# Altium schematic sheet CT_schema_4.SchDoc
size 573 x 376 mm
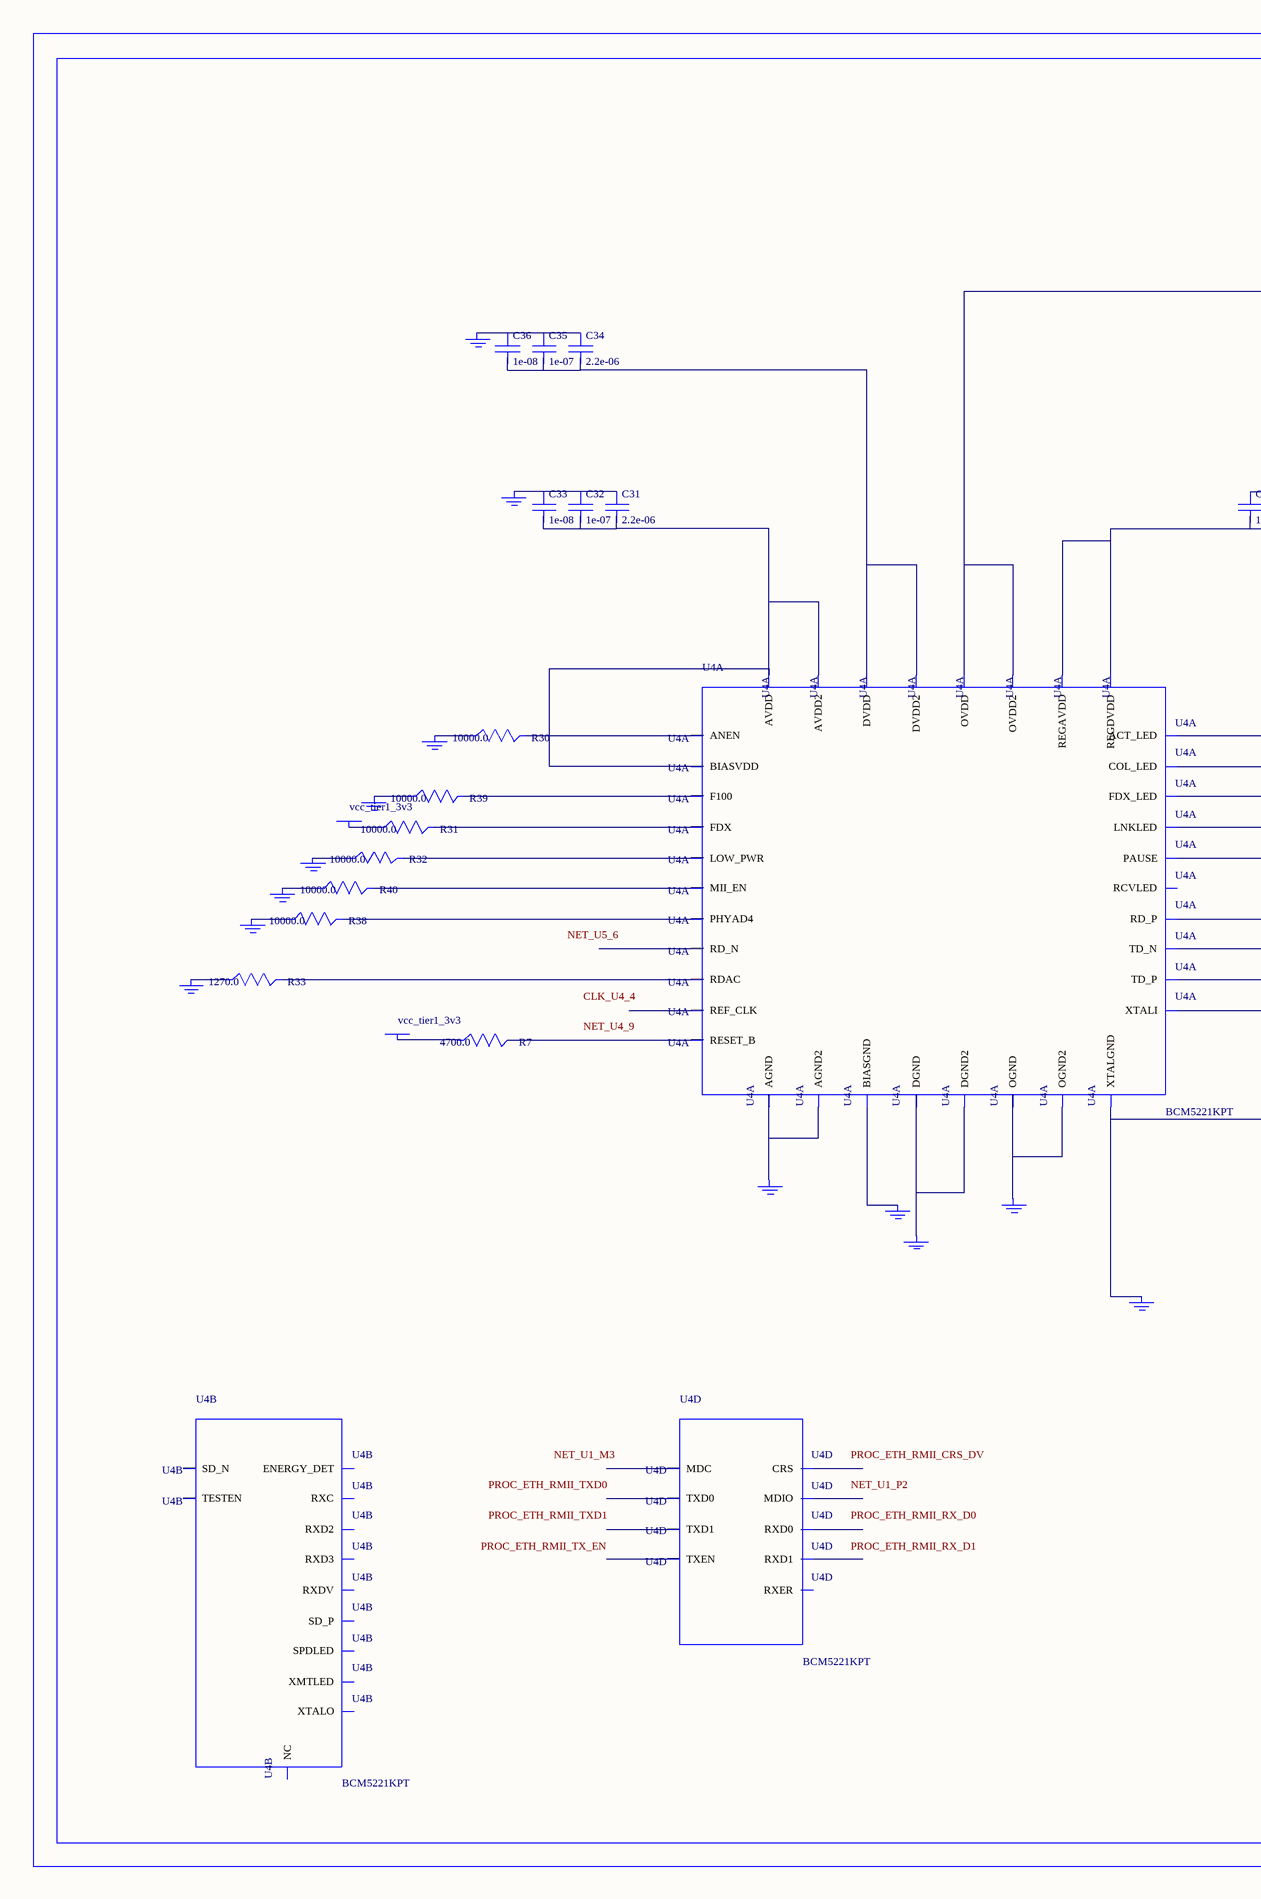
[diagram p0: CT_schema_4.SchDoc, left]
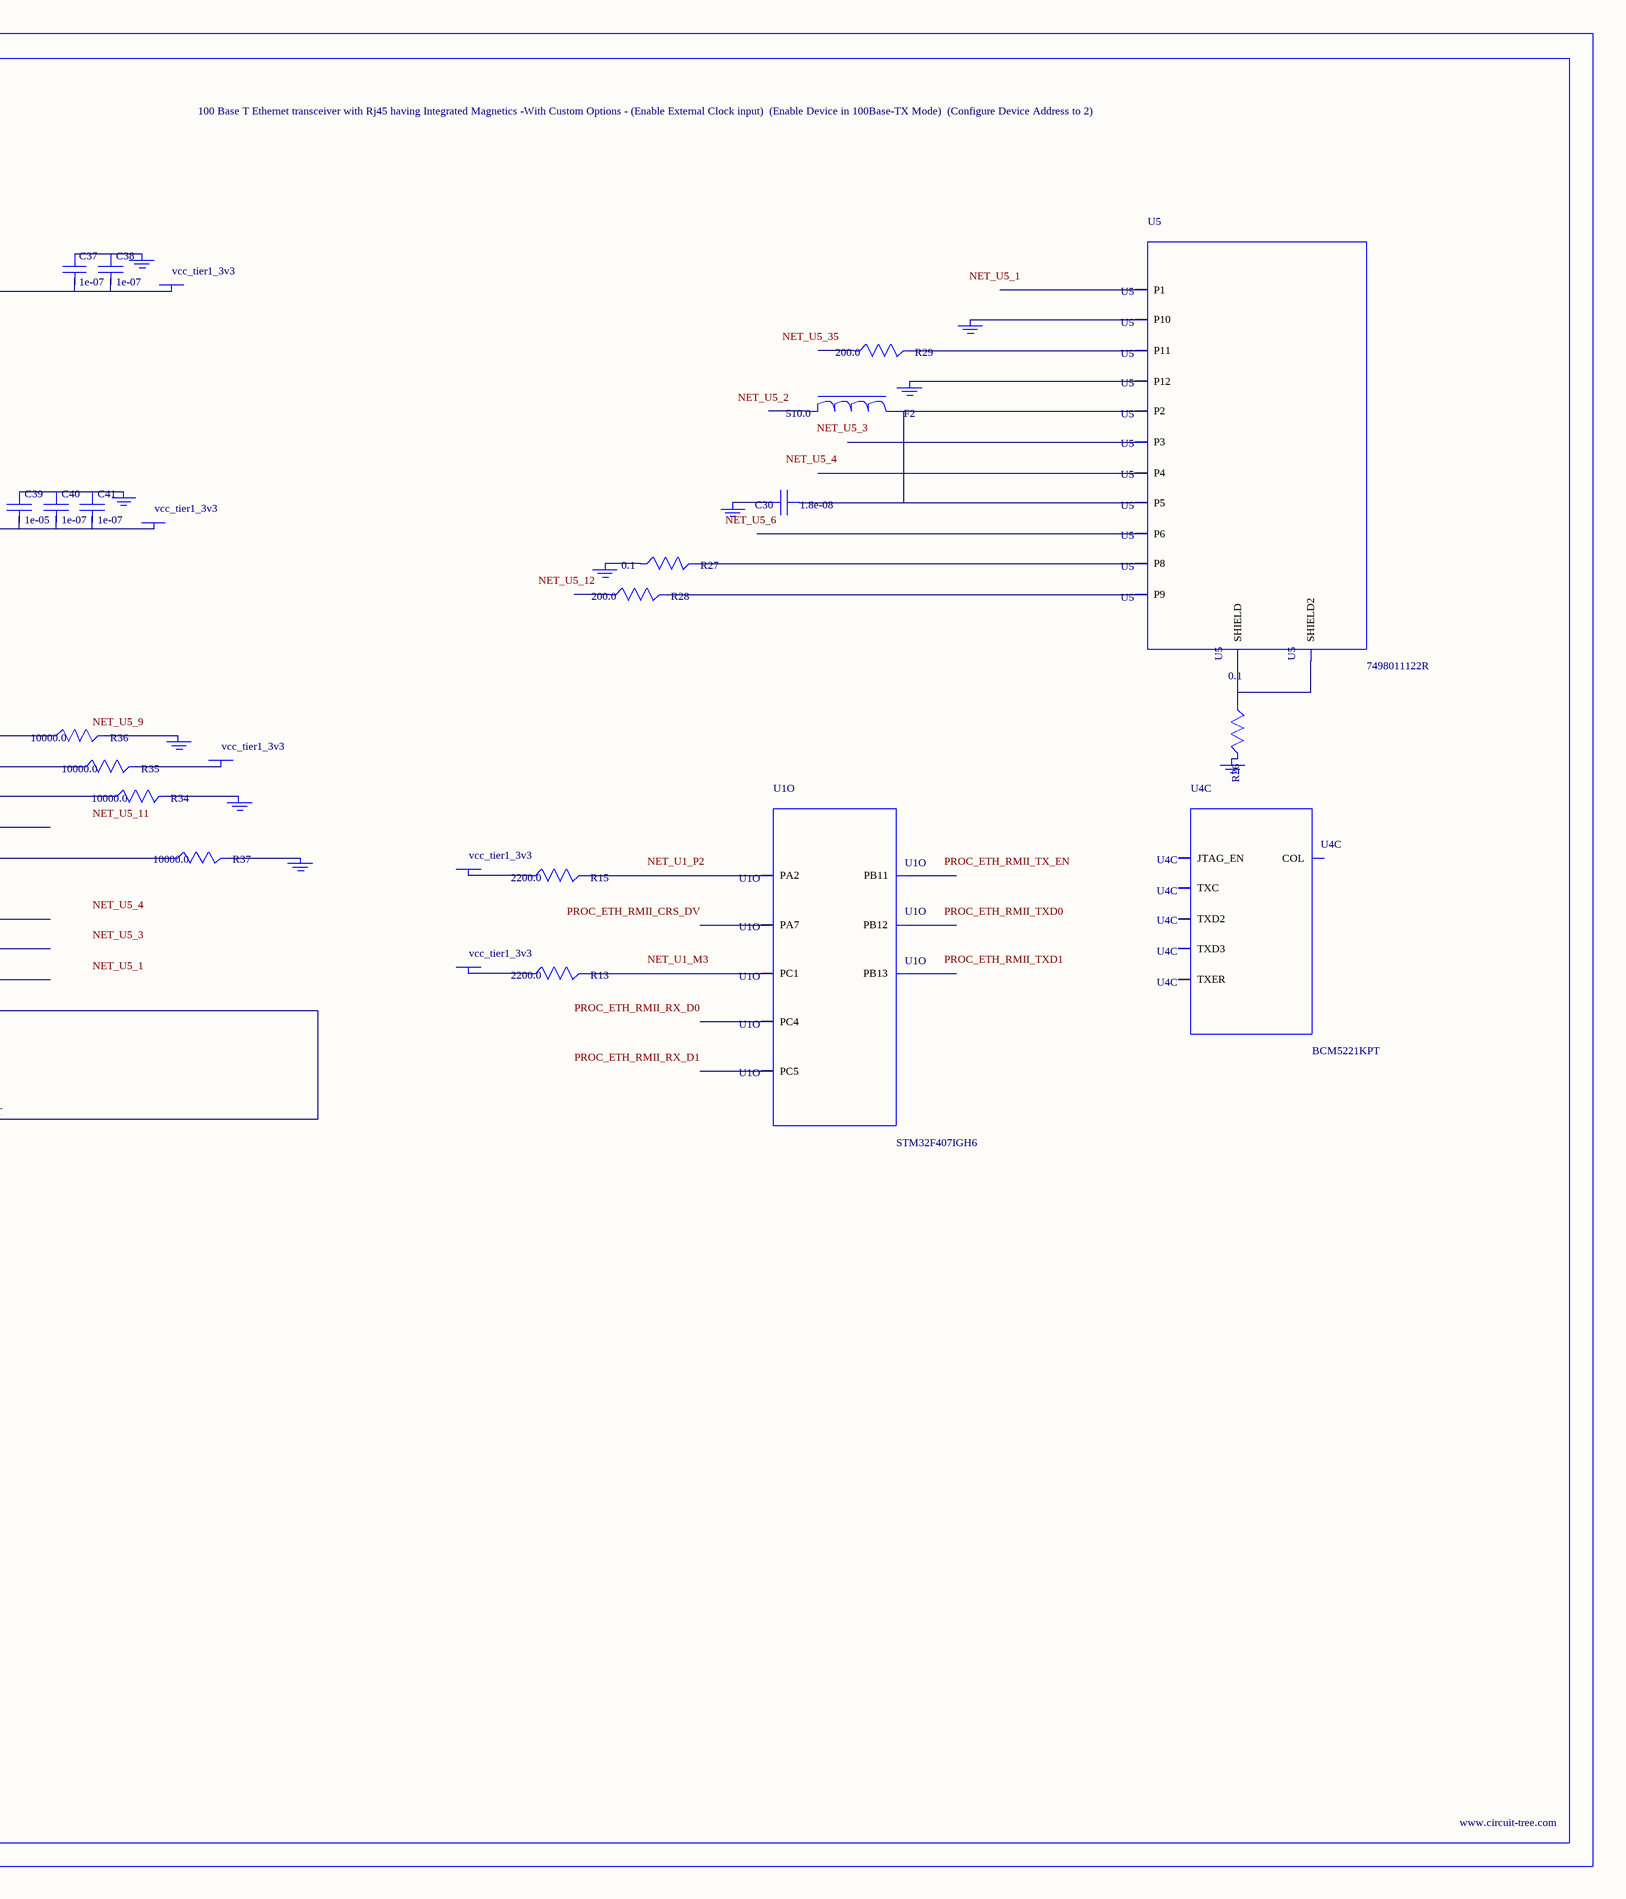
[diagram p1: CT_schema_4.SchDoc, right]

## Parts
BORDER3  (no value)
C30  1.8e-08  [C0402]
C31  2.2e-06  [C0603]
C32  1e-07  [C0402]
C33  1e-08  [C0402]
C34  2.2e-06  [C0603]
C35  1e-07  [C0402]
C36  1e-08  [C0402]
C37  1e-07  [C0402]
C38  1e-07  [C0402]
C39  1e-05  [C0805]
C40  1e-07  [C0402]
C41  1e-07  [C0402]
F2  510.0  [L0603]
GND_INSTANCE_3_0  (no value)
GND_INSTANCE_3_1  (no value)
GND_INSTANCE_3_2  (no value)
GND_INSTANCE_3_3  (no value)
GND_INSTANCE_3_4  (no value)
GND_INSTANCE_3_5  (no value)
GND_INSTANCE_3_6  (no value)
GND_INSTANCE_3_7  (no value)
GND_INSTANCE_3_8  (no value)
GND_INSTANCE_3_9  (no value)
GND_INSTANCE_3_10  (no value)
GND_INSTANCE_3_11  (no value)
GND_INSTANCE_3_12  (no value)
GND_INSTANCE_3_13  (no value)
GND_INSTANCE_3_14  (no value)
GND_INSTANCE_3_15  (no value)
GND_INSTANCE_3_16  (no value)
GND_INSTANCE_3_17  (no value)
GND_INSTANCE_3_18  (no value)
GND_INSTANCE_3_19  (no value)
GND_INSTANCE_3_20  (no value)
GND_INSTANCE_3_21  (no value)
GND_INSTANCE_3_22  (no value)
POWER_INSTANCE_3_0  vcc_tier1_3v3
POWER_INSTANCE_3_1  vcc_tier1_3v3
POWER_INSTANCE_3_2  vcc_tier1_3v3
POWER_INSTANCE_3_3  vcc_tier1_3v3
POWER_INSTANCE_3_4  vcc_tier1_3v3
POWER_INSTANCE_3_5  vcc_tier1_3v3
POWER_INSTANCE_3_6  vcc_tier1_3v3
R7  4700.0  [R0603]
R13  2200.0  [R0603]
R15  2200.0  [R0603]
R26  0.1  [R0603]
R27  0.1  [R0603]
R28  200.0  [R0603]
R29  200.0  [R0603]
R30  10000.0  [R0603]
R31  10000.0  [R0603]
R32  10000.0  [R0603]
R33  1270.0  [R0603]
R34  10000.0  [R0603]
R35  10000.0  [R0603]
R36  10000.0  [R0603]
R37  10000.0  [R0603]
R38  10000.0  [R0603]
R39  10000.0  [R0603]
R40  10000.0  [R0603]
U1  STM32F407IGH6  [UFBGA176]  (part O of 18)
U4  BCM5221KPT  [TQFP64_10X10MC]  (parts A,B,C,D of 4)
U5  7498011122R  [7498011122R]

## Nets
NetC30_1: C30.1 F2.2 U5.2(P2) U5.5(P5)
NetC30_2: C30.2 GND_INSTANCE_3_18.0(GND)
NetC31_1: C31.1 C32.1 C33.1 GND_INSTANCE_3_12.0(GND)
NetC31_2: C31.2 C32.2 C33.2 U4.22(BIASVDD) U4.27(AVDD) U4.28(AVDD2)
NetC34_1: C34.1 C35.1 C36.1 GND_INSTANCE_3_1.0(GND)
NetC34_2: C34.2 C35.2 C36.2 U4.2(DVDD) U4.55(DVDD2)
NetC37_1: C37.1 C38.1 GND_INSTANCE_3_0.0(GND)
NetC37_2: C37.2 C38.2 POWER_INSTANCE_3_0.0(PWR) U4.1(OVDD) U4.46(OVDD2)
NetC39_1: C39.1 C40.1 C41.1 GND_INSTANCE_3_2.0(GND)
NetC39_2: C39.2 C40.2 C41.2 POWER_INSTANCE_3_1.0(PWR) U4.3(REGDVDD) U4.20(REGAVDD)
NetGND_INSTANCE_3_3_0: GND_INSTANCE_3_3.0(GND) U4.6(XTALI) U4.7(XTALGND)
NetGND_INSTANCE_3_4_0: GND_INSTANCE_3_4.0(GND) R34.2
NetGND_INSTANCE_3_5_0: GND_INSTANCE_3_5.0(GND) R36.2
NetGND_INSTANCE_3_6_0: GND_INSTANCE_3_6.0(GND) R37.2
NetGND_INSTANCE_3_7_0: GND_INSTANCE_3_7.0(GND) R38.1
NetGND_INSTANCE_3_8_0: GND_INSTANCE_3_8.0(GND) R32.1
NetGND_INSTANCE_3_9_0: GND_INSTANCE_3_9.0(GND) R40.1
NetGND_INSTANCE_3_10_0: GND_INSTANCE_3_10.0(GND) R33.1
NetGND_INSTANCE_3_11_0: GND_INSTANCE_3_11.0(GND) U4.24(BIASGND)
NetGND_INSTANCE_3_13_0: GND_INSTANCE_3_13.0(GND) R39.1
NetGND_INSTANCE_3_14_0: GND_INSTANCE_3_14.0(GND) R30.1
NetGND_INSTANCE_3_15_0: GND_INSTANCE_3_15.0(GND) U4.29(AGND) U4.32(AGND2)
NetGND_INSTANCE_3_16_0: GND_INSTANCE_3_16.0(GND) U4.40(OGND) U4.45(OGND2)
NetGND_INSTANCE_3_17_0: GND_INSTANCE_3_17.0(GND) U4.54(DGND) U4.63(DGND2)
NetGND_INSTANCE_3_19_0: GND_INSTANCE_3_19.0(GND) R27.1
NetGND_INSTANCE_3_20_0: GND_INSTANCE_3_20.0(GND) U5.10(P10)
NetGND_INSTANCE_3_21_0: GND_INSTANCE_3_21.0(GND) U5.12(P12)
NetGND_INSTANCE_3_22_0: GND_INSTANCE_3_22.0(GND) R26.2
NetPOWER_INSTANCE_3_2_0: POWER_INSTANCE_3_2.0(PWR) R35.2
NetPOWER_INSTANCE_3_3_0: POWER_INSTANCE_3_3.0(PWR) R31.1
NetPOWER_INSTANCE_3_4_0: POWER_INSTANCE_3_4.0(PWR) R7.1
NetPOWER_INSTANCE_3_5_0: POWER_INSTANCE_3_5.0(PWR) R15.1
NetPOWER_INSTANCE_3_6_0: POWER_INSTANCE_3_6.0(PWR) R13.1
NetR7_2: R7.2 U4.9(RESET_B)
NetR13_2: R13.2 U1.M3(PC1)
NetR15_2: R15.2 U1.P2(PA2)
NetR26_1: R26.1 U5.13(SHIELD) U5.14(SHIELD2)
NetR27_2: R27.2 U5.8(P8)
NetR28_2: R28.2 U5.9(P9)
NetR29_2: R29.2 U5.11(P11)
NetR30_2: R30.2 U4.38(ANEN)
NetR31_2: R31.2 U4.39(FDX)
NetR32_2: R32.2 U4.16(LOW_PWR)
NetR33_2: R33.2 U4.23(RDAC)
NetR34_1: R34.1 U4.10(FDX_LED)
NetR35_1: R35.1 U4.11(COL_LED)
NetR36_1: R36.1 U4.12(ACT_LED)
NetR37_1: R37.1 U4.13(PAUSE)
NetR38_2: R38.2 U4.14(PHYAD4)
NetR39_2: R39.2 U4.37(F100)
NetR40_2: R40.2 U4.18(MII_EN)

Not connected (* = marked no-connect by the designer): F2 1; R28 1; R29 1; U1 N5(PC4) P5(PC5) P12(PB12) P13(PB13) R3(PA7) R13(PB11); U4 4(REF_CLK) 5(XTALO) 8(NC) 15(TESTEN) 17(ENERGY_DET) 19(SD_N) 21(SD_P) 25(RD_N) 26(RD_P) 30(TD_N) 31(TD_P) 33(RCVLED) 34(XMTLED) 35(LNKLED) 36(SPDLED) 41(MDIO) 42(MDC) 43(RXD3) 44(RXD2) 47(RXD1) 48(RXD0) 49(RXDV) 50(RXC) 51(RXER) 52(TXER) 53(TXC) 56(TXEN) 57(TXD0) 58(TXD1) 59(TXD2) 60(TXD3) 61(COL) 62(CRS) 64(JTAG_EN); U5 1(P1) 3(P3) 4(P4) 6(P6)

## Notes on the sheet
- Labels drawn without touching a wire or pin: CLK_U4_4, NET_U1_M3, NET_U1_P2, NET_U4_9, NET_U5_1, NET_U5_2, NET_U5_3, NET_U5_4, NET_U5_6, NET_U5_9, NET_U5_11, NET_U5_12, NET_U5_35, PROC_ETH_RMII_CRS_DV, PROC_ETH_RMII_RX_D0, PROC_ETH_RMII_RX_D1, PROC_ETH_RMII_TX_EN, PROC_ETH_RMII_TXD0, PROC_ETH_RMII_TXD1

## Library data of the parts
BORDER3 = BORDER_PAGE3
C30 = C0402C183K3RAC
C31 C34 = C0603C225K8RACTU
C32 C35 C37 C38 C40 C41 = C0402C104K3RACTU
C33 C36 = C0402C103K3RAC
C39 = C0805C106K8RACTU
F2 = ERA3APB511V
GND_INSTANCE_3_0-GND_INSTANCE_3_22 = GND
POWER_INSTANCE_3_0-POWER_INSTANCE_3_6 = PWR
R7 = RC0603JR-074K7L
R13 R15 = RC0603JR-072K2L
R26 R27 = ERJ-3RSFR10V
R28 R29 = RC0603JR-07200RL
R30-R32 R34-R40 = RC0603JR-0710KL
R33 = RC0603FR-071K27L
